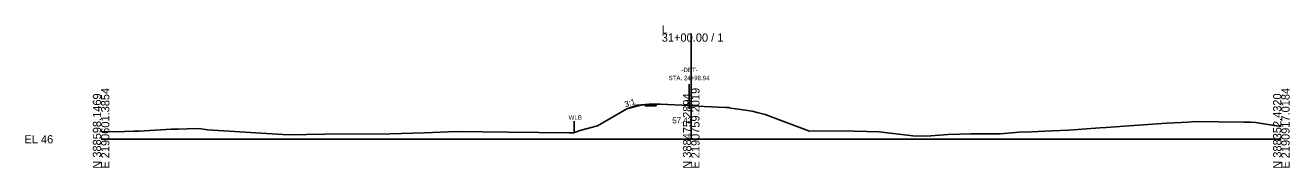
# Model space of a CAD drawing. Extents: x -26 to 2190750, y -10 to 388496.
# Drawn here: x 974.3 to 1402.8, y 4990.3 to 5038.8 of the extents above; entities that cross this region are included whole.
import ezdxf

# ---------------------------------------------------------------- set-up
doc = ezdxf.new("R2010")
doc.units = 0
for name, color, linetype in [('Default', 7, 'Continuous'), ('Exist Cross Section Cell', 7, 'Continuous'), ('Exist XS Center Line Elevation Label', 7, 'Continuous'), ('Exist XS Ground Line', 7, 'Continuous'), ('Prop CMT Pvmt Course 1', 7, 'Continuous'), ('Prop CMT Pvmt Course 2', 7, 'Continuous'), ('Prop CMT Pvmt Course 3', 7, 'Continuous'), ('Prop CMT Pvmt Surface', 7, 'Continuous'), ('Prop CMT Pvmt Surface Shoulder', 7, 'Continuous'), ('Prop CMT Shld Paved Course 1', 7, 'Continuous'), ('Prop CMT Shld Paved Course 2', 7, 'Continuous'), ('Prop CMT Shld Paved Course 3', 7, 'Continuous'), ('Prop CMT Slope Grass', 7, 'Continuous'), ('Prop CMT Subgrade Earthwork', 7, 'Continuous'), ('Prop RDY Alternate Text Blue', 7, 'Continuous'), ('Prop XS Alignment Label', 7, 'Continuous'), ('Prop XS Side Slope Text', 7, 'Continuous')]:
    doc.layers.add(name, color=color, linetype=linetype)

msp = doc.modelspace()

# ---------------------------------------------------------------- linework, layer by layer
at = {"layer": 'Exist Cross Section Cell'}
for p, q in [((1200, 5000), (1200, 5035.99)), ((1000, 5000), (1200, 5000)), ((1200, 5000), (1400, 5000))]:
    msp.add_line(p, q, dxfattribs=at)
at = {"layer": 'Exist XS Ground Line'}
msp.add_lwpolyline([(1000, 5002.68), (1004.75, 5002.49), (1011.13, 5002.72), (1012.85, 5002.8), (1023.8, 5003.4), (1026.13, 5003.44), (1029.13, 5003.61), (1033.26, 5003.69), (1036.03, 5003.27), (1063.37, 5001.5), (1075.81, 5001.76), (1097.9, 5001.9), (1109.62, 5002.2), (1120.43, 5002.64), (1138.11, 5002.47), (1158.64, 5002.24), (1160.07, 5002.24), (1162.71, 5003.12), (1168.2, 5004.54), (1178.13, 5010.41), (1183.01, 5011.63), (1186.04, 5011.86), (1187.46, 5011.97), (1188.07, 5012), (1189.59, 5011.94), (1199.14, 5011.46), (1200, 5011.42), (1200.81, 5011.38), (1204.38, 5011.2), (1211.77, 5010.84), (1212.63, 5010.76), (1212.99, 5010.72), (1213.42, 5010.63), (1216.81, 5010.11), (1220.68, 5009.52), (1222.39, 5009.09), (1225.06, 5008.43), (1232.82, 5005.46), (1240.08, 5002.73), (1251.15, 5002.89), (1263.65, 5002.58), (1275.12, 5001.16), (1279.71, 5001.09), (1287.1, 5001.62), (1294.77, 5001.88), (1304.68, 5001.91), (1311.19, 5002.42), (1315.31, 5002.58), (1322.18, 5002.82), (1327.98, 5003.1), (1338.46, 5003.84), (1340.65, 5004.04), (1348.38, 5004.54), (1353.33, 5004.9), (1354.74, 5005), (1361.07, 5005.43), (1366, 5005.73), (1368.2, 5005.77), (1371.02, 5006.02), (1378.68, 5005.97), (1387.3, 5005.77), (1389.58, 5005.87), (1391.38, 5005.67), (1393.39, 5005.41), (1400, 5004.35)], dxfattribs=at)
at = {"layer": 'Prop CMT Pvmt Course 1'}
for points in [[(1187.77, 5012), (1188.07, 5012)], [(1187.77, 5012), (1187.77, 5011.75)], [(1188.07, 5011.75), (1187.77, 5011.75)]]:
    msp.add_lwpolyline(points, dxfattribs=at)
at = {"layer": 'Prop CMT Pvmt Course 2'}
for points in [[(1185.26, 5011.8), (1185.26, 5011.8)], [(1188.07, 5011.75), (1187.77, 5011.75)], [(1187.77, 5011.75), (1187.77, 5011.75)]]:
    msp.add_lwpolyline(points, dxfattribs=at)
at = {"layer": 'Prop CMT Pvmt Course 3'}
for points in [[(1187.77, 5011.75), (1188.07, 5011.75)], [(1187.77, 5011.75), (1187.77, 5011.38)], [(1188.07, 5011.37), (1187.77, 5011.38)]]:
    msp.add_lwpolyline(points, dxfattribs=at)
at = {"layer": 'Prop CMT Pvmt Surface'}
msp.add_lwpolyline([(1187.77, 5012), (1188.07, 5012)], dxfattribs=at)
at = {"layer": 'Prop CMT Pvmt Surface Shoulder'}
msp.add_lwpolyline([(1187.77, 5012), (1185.76, 5011.96)], dxfattribs=at)
at = {"layer": 'Prop CMT Shld Paved Course 1'}
for points in [[(1187.77, 5012), (1185.76, 5011.96), (1185.5, 5011.71)], [(1185.5, 5011.71), (1187.77, 5011.75)], [(1187.77, 5011.75), (1187.77, 5012)]]:
    msp.add_lwpolyline(points, dxfattribs=at)
at = {"layer": 'Prop CMT Shld Paved Course 2'}
for points in [[(1185.26, 5011.8), (1185.26, 5011.8)], [(1187.77, 5011.75), (1185.5, 5011.71)], [(1185.5, 5011.71), (1185.5, 5011.71)], [(1187.77, 5011.75), (1187.77, 5011.75)]]:
    msp.add_lwpolyline(points, dxfattribs=at)
at = {"layer": 'Prop CMT Shld Paved Course 3'}
for points in [[(1187.77, 5011.75), (1185.5, 5011.71), (1184.99, 5011.7), (1184.61, 5011.32)], [(1184.61, 5011.32), (1187.77, 5011.38)], [(1187.77, 5011.38), (1187.77, 5011.75)]]:
    msp.add_lwpolyline(points, dxfattribs=at)
at = {"layer": 'Prop CMT Slope Grass'}
for q in [(1178.13, 5010.41), (1185.76, 5011.96)]:
    msp.add_line((1181.72, 5011.64), q, dxfattribs=at)
at = {"layer": 'Prop CMT Subgrade Earthwork'}
for points in [[(1184.61, 5011.32), (1184.09, 5011.83)], [(1187.77, 5011.38), (1184.61, 5011.32)], [(1187.77, 5011.38), (1188.07, 5011.37)], [(1188.07, 5012), (1188.07, 5011.37)]]:
    msp.add_lwpolyline(points, dxfattribs=at)
at = {"layer": 'Prop RDY Alternate Text Blue'}
msp.add_line((1160.37, 5006.16), (1160.37, 5002.34), dxfattribs=at)
at = {"layer": 'Prop XS Alignment Label'}
msp.add_line((1199.34, 5018.72), (1199.34, 5010.38), dxfattribs=at)

# ---------------------------------------------------------------- texts
at = {"layer": 'Default'}
msp.add_text('-', height=0.0001, dxfattribs=at).set_placement((1000, 5000))
at = {"layer": 'Exist Cross Section Cell'}
for s, p in [('31+00.00 / 1', (1190, 5033.19)), ('L', (1190, 5035.99)), ('EL 46', (974, 4998.6))]:
    msp.add_text(s, height=2.8, dxfattribs=at).set_placement(p)
for s, p in [('N 388598.1469', (1000, 4990)), ('E 2190601.3854', (1002.8, 4990)), ('N 388475.2894', (1200, 4990)), ('E 2190759.2019', (1202.8, 4990)), ('N 388352.4320', (1400, 4990)), ('E 2190917.0184', (1402.8, 4990))]:
    msp.add_text(s, height=2.8, rotation=90, dxfattribs=at).set_placement(p)
at = {"layer": 'Exist XS Center Line Elevation Label'}
msp.add_text('57.42', height=2, dxfattribs=at).set_placement((1193.57, 5005.42))
at = {"layer": 'Prop RDY Alternate Text Blue'}
msp.add_text('WLB', height=1.5, dxfattribs=at).set_placement((1158.45, 5006.63))
at = {"layer": 'Prop XS Alignment Label'}
for s, p in [('-DET-', (1196.68, 5022.85)), ('STA. 24+98.94', (1192.33, 5020.1))]:
    msp.add_text(s, height=1.5, dxfattribs=at).set_placement(p)
at = {"layer": 'Prop XS Side Slope Text'}
msp.add_text('3:1', height=2, rotation=18.4349, dxfattribs=at).set_placement((1177.76, 5010.83))

doc.saveas('drawing.dxf')
